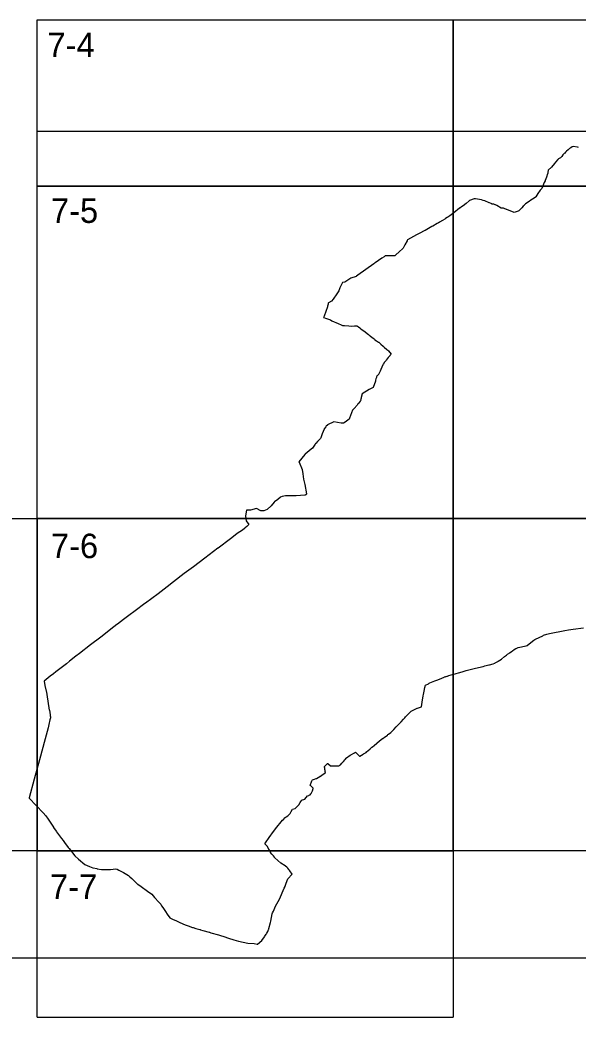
# Model space of a CAD drawing. Extents: x -449577 to -425530, y -1150048 to -1121091.
# Drawn here: x -431675.5 to -431465.8, y -1126653.4 to -1126278.4 of the extents above; entities that cross this region are included whole.
import ezdxf

# ---------------------------------------------------------------- set-up
doc = ezdxf.new("R2010")
doc.units = 0
for name, color, linetype in [('Vrstva 1', 7, 'Continuous'), ('Vrstva 10', 7, 'Continuous'), ('Vrstva 4', 7, 'Continuous')]:
    doc.layers.add(name, color=color, linetype=linetype)

msp = doc.modelspace()

# ---------------------------------------------------------------- linework, layer by layer
at = {"layer": 'Vrstva 1'}
for points in [[(-431465.6, -1126326.41), (-431466.06, -1126326.32), (-431467.65, -1126326), (-431467.95, -1126326.11), (-431468.51, -1126326.46), (-431469.06, -1126326.78), (-431469.55, -1126327.24), (-431470.08, -1126327.73), (-431470.48, -1126328.12), (-431470.49, -1126328.13), (-431470.82, -1126328.47), (-431470.95, -1126328.61), (-431471.46, -1126329.16), (-431471.91, -1126329.71), (-431472.07, -1126329.9), (-431472.43, -1126330.33), (-431473.17, -1126330.66), (-431473.19, -1126330.66), (-431473.39, -1126330.91), (-431474.25, -1126331.93), (-431474.63, -1126332.38), (-431475.76, -1126333.74), (-431475.77, -1126333.75), (-431477.01, -1126334.92), (-431477.13, -1126335.76), (-431477.18, -1126336.13), (-431477.22, -1126336.23), (-431477.7, -1126337.58), (-431478.14, -1126338.82), (-431478.17, -1126338.9), (-431478.47, -1126339.59), (-431479.4, -1126341.77), (-431479.42, -1126341.78), (-431479.99, -1126342.46), (-431480.29, -1126342.81), (-431480.29, -1126342.82), (-431480.63, -1126343.36), (-431481.5, -1126344.75), (-431481.59, -1126344.89), (-431481.76, -1126345.02), (-431482.29, -1126345.41), (-431482.9, -1126345.86), (-431482.9, -1126345.86), (-431483.87, -1126346.49), (-431484, -1126346.58), (-431484.18, -1126346.7), (-431485.48, -1126347.56), (-431485.49, -1126347.57), (-431485.75, -1126347.83), (-431485.87, -1126347.95), (-431486.09, -1126348.18), (-431486.37, -1126348.46), (-431486.94, -1126349.03), (-431488.1, -1126350.19), (-431488.3, -1126350.27), (-431489.8, -1126350.84), (-431492.61, -1126349.72), (-431492.61, -1126349.73), (-431492.62, -1126349.75), (-431493.53, -1126349.37), (-431493.84, -1126349.24), (-431493.86, -1126349.24), (-431494.25, -1126349.24), (-431494.73, -1126349.24), (-431496.29, -1126348.25), (-431496.55, -1126348.12), (-431496.84, -1126347.96), (-431496.9, -1126347.93), (-431496.94, -1126347.91), (-431497.48, -1126347.68), (-431497.53, -1126347.68), (-431497.54, -1126347.68), (-431497.69, -1126347.67), (-431497.81, -1126347.66), (-431498.12, -1126347.64), (-431498.14, -1126347.64), (-431498.14, -1126347.64), (-431498.25, -1126347.6), (-431498.49, -1126347.5), (-431499.09, -1126347.25), (-431499.25, -1126347.18), (-431500.77, -1126346.45), (-431501.39, -1126346.27), (-431502.06, -1126346.07), (-431504.38, -1126345.64), (-431504.39, -1126345.64), (-431504.79, -1126345.75), (-431506.53, -1126346.33), (-431506.66, -1126346.44), (-431507.87, -1126347.4), (-431507.87, -1126347.4), (-431509.02, -1126348.27), (-431509.59, -1126348.7), (-431510.17, -1126349.14), (-431510.33, -1126349.26), (-431512.46, -1126350.9), (-431513.53, -1126351.72), (-431514, -1126352.06), (-431514.76, -1126352.57), (-431515.01, -1126352.73), (-431515.6, -1126353.12), (-431515.64, -1126353.15), (-431515.85, -1126353.29), (-431516.76, -1126353.89), (-431516.77, -1126353.89), (-431517.24, -1126354.15), (-431517.39, -1126354.23), (-431517.57, -1126354.33), (-431518.03, -1126354.58), (-431518.21, -1126354.69), (-431518.37, -1126354.78), (-431518.47, -1126354.84), (-431518.71, -1126354.98), (-431520.37, -1126355.92), (-431520.54, -1126356.01), (-431520.77, -1126356.14), (-431523.24, -1126357.54), (-431523.36, -1126357.61), (-431525.47, -1126358.74), (-431526.49, -1126359.29), (-431529.83, -1126361.1), (-431530, -1126361.4), (-431530.06, -1126361.51), (-431530.84, -1126362.97), (-431531.52, -1126364.29), (-431531.66, -1126364.42), (-431531.75, -1126364.5), (-431532.89, -1126365.54), (-431534.4, -1126366.92), (-431534.57, -1126367.07), (-431534.57, -1126367.08), (-431535.04, -1126367.09), (-431538.23, -1126367.18), (-431538.24, -1126367.18), (-431538.67, -1126367.47), (-431539.5, -1126368.04), (-431541.97, -1126369.7), (-431542.01, -1126369.72), (-431542.25, -1126369.9), (-431542.52, -1126370.1), (-431545.5, -1126372.23), (-431545.57, -1126372.28), (-431548.57, -1126374.46), (-431549.04, -1126374.8), (-431549.2, -1126374.86), (-431551.14, -1126375.58), (-431551.15, -1126375.58), (-431551.54, -1126375.82), (-431553.42, -1126376.98), (-431554.34, -1126377.19), (-431554.59, -1126377.7), (-431555.35, -1126379.21), (-431555.36, -1126379.22), (-431555.43, -1126379.48), (-431555.63, -1126380.32), (-431556.46, -1126381.43), (-431557.83, -1126383.38), (-431558.39, -1126384.19), (-431558.42, -1126384.21), (-431559.58, -1126384.85), (-431559.68, -1126384.91), (-431559.75, -1126385.3), (-431559.9, -1126386.11), (-431559.95, -1126386.3), (-431561.24, -1126389.88), (-431561.41, -1126390.36), (-431561.38, -1126390.35), (-431561.36, -1126390.34), (-431560.68, -1126390.6), (-431558.87, -1126391.26), (-431558.25, -1126391.55), (-431555.96, -1126392.63), (-431555.94, -1126392.63), (-431554.78, -1126393.1), (-431554.31, -1126393.28), (-431554.28, -1126393.29), (-431553.85, -1126393.32), (-431553.71, -1126393.33), (-431553.49, -1126393.35), (-431551.89, -1126393.45), (-431550.85, -1126393.52), (-431549.8, -1126393.49), (-431548.96, -1126393.46), (-431548.95, -1126393.46), (-431548.67, -1126393.61), (-431548.3, -1126393.87), (-431547.75, -1126394.25), (-431547.36, -1126394.53), (-431545.8, -1126395.67), (-431545.63, -1126395.79), (-431544.52, -1126396.71), (-431544.13, -1126397.03), (-431543.95, -1126397.18), (-431543.2, -1126397.79), (-431542.93, -1126398.02), (-431542.33, -1126398.51), (-431542.11, -1126398.69), (-431541.47, -1126399.11), (-431540.72, -1126399.61), (-431540.69, -1126399.63), (-431539.93, -1126400.31), (-431539.05, -1126401.09), (-431538.61, -1126401.47), (-431537.6, -1126402.36), (-431537.34, -1126402.59), (-431537.29, -1126402.64), (-431537.19, -1126402.74), (-431537.18, -1126402.75), (-431537.09, -1126402.85), (-431537.06, -1126402.88), (-431536.01, -1126404.11), (-431536.02, -1126404.12), (-431536.46, -1126404.61), (-431536.52, -1126404.68), (-431537.09, -1126405.31), (-431537.91, -1126406.37), (-431538.08, -1126406.58), (-431538.64, -1126407.3), (-431538.94, -1126407.83), (-431538.96, -1126407.87), (-431538.97, -1126407.89), (-431539.1, -1126408.17), (-431539.9, -1126409.84), (-431540.21, -1126410.48), (-431540.83, -1126411.77), (-431540.94, -1126412.01), (-431540.95, -1126412.01), (-431540.99, -1126412.04), (-431541.28, -1126412.24), (-431541.36, -1126412.28), (-431541.41, -1126412.38), (-431541.5, -1126412.58), (-431541.59, -1126412.86), (-431541.76, -1126413.42), (-431541.77, -1126413.44), (-431541.89, -1126413.94), (-431541.91, -1126414.01), (-431541.9, -1126414.07), (-431541.89, -1126414.15), (-431541.89, -1126414.22), (-431541.9, -1126414.27), (-431542.78, -1126416.6), (-431542.8, -1126416.65), (-431542.82, -1126416.69), (-431542.83, -1126416.7), (-431543.53, -1126417), (-431543.78, -1126417.11), (-431544.25, -1126417.35), (-431546.86, -1126419.04), (-431546.86, -1126419.04), (-431547.23, -1126420.35), (-431547.31, -1126420.61), (-431547.42, -1126421.03), (-431547.48, -1126421.24), (-431547.48, -1126421.25), (-431547.47, -1126421.25), (-431547.3, -1126421.41), (-431547.31, -1126421.42), (-431547.67, -1126421.81), (-431548.47, -1126422.81), (-431548.48, -1126422.82), (-431548.69, -1126423.07), (-431548.69, -1126423.08), (-431548.81, -1126423.23), (-431549.97, -1126424.58), (-431550.51, -1126425.21), (-431551.27, -1126427.16), (-431551.65, -1126428.18), (-431551.78, -1126428.53), (-431553.31, -1126429.63), (-431553.93, -1126430.07), (-431554.11, -1126430.11), (-431554.13, -1126430.11), (-431554.76, -1126430.02), (-431557.6, -1126429.6), (-431558.09, -1126429.84), (-431559.42, -1126430.48), (-431559.96, -1126430.74), (-431559.99, -1126430.77), (-431560.42, -1126431.18), (-431560.59, -1126431.4), (-431561.25, -1126432.25), (-431561.25, -1126432.26), (-431561.92, -1126434.06), (-431562.49, -1126435.56), (-431562.49, -1126435.56), (-431562.63, -1126435.78), (-431562.96, -1126436.15), (-431563.68, -1126436.95), (-431564.38, -1126437.72), (-431564.39, -1126437.74), (-431564.52, -1126437.93), (-431565.59, -1126439.5), (-431566.06, -1126439.88), (-431567.63, -1126441.14), (-431568.3, -1126441.68), (-431568.4, -1126441.76), (-431568.43, -1126441.8), (-431569.55, -1126443.23), (-431570.69, -1126444.54), (-431570.54, -1126444.71), (-431570.53, -1126444.74), (-431570.53, -1126444.75), (-431569.52, -1126447.51), (-431569.24, -1126449.17), (-431568.92, -1126451.12), (-431568.51, -1126453.08), (-431567.78, -1126456.58), (-431567.74, -1126456.78), (-431568.39, -1126457.12), (-431568.51, -1126457.19), (-431571.68, -1126457.45), (-431571.84, -1126457.45), (-431573.33, -1126457.42), (-431575.72, -1126457.4), (-431577, -1126457.67), (-431577.6, -1126457.94), (-431578.58, -1126458.74), (-431579.88, -1126459.61), (-431579.97, -1126459.72), (-431581.13, -1126461.14), (-431582.58, -1126462.48), (-431583.27, -1126462.8), (-431583.87, -1126463.08), (-431585.04, -1126463.01), (-431586.65, -1126462.16), (-431588.89, -1126462.83), (-431590.37, -1126462.8), (-431590.75, -1126464.91), (-431590.76, -1126464.93), (-431590.77, -1126465.02), (-431590.48, -1126466.83), (-431589.51, -1126468.15), (-431589.5, -1126468.17), (-431590.24, -1126468.92), (-431590.85, -1126469.48), (-431591.1, -1126469.71), (-431591.9, -1126470.34), (-431593.83, -1126471.57), (-431593.89, -1126471.61), (-431595.86, -1126473.14), (-431595.92, -1126473.18), (-431596.41, -1126473.56), (-431601.07, -1126477.02), (-431601.1, -1126477.05), (-431606.05, -1126480.81), (-431610.31, -1126484.06), (-431611.19, -1126484.72), (-431613.76, -1126486.66), (-431617.76, -1126489.79), (-431620.2, -1126491.66), (-431623.51, -1126494.19), (-431623.56, -1126494.23), (-431628.35, -1126497.74), (-431628.58, -1126497.92), (-431632.19, -1126500.6), (-431634.58, -1126502.42), (-431636.55, -1126503.9), (-431638.87, -1126505.65), (-431639.1, -1126505.82), (-431640.23, -1126506.71), (-431645.05, -1126510.51), (-431648.94, -1126513.46), (-431653.16, -1126516.71), (-431654.45, -1126517.71), (-431656.84, -1126519.59), (-431658.02, -1126520.51), (-431661.96, -1126523.56), (-431662.89, -1126524.27), (-431664.13, -1126525.23), (-431666.45, -1126527.03), (-431666.45, -1126527.03), (-431666.41, -1126527.21), (-431666.12, -1126528.59), (-431666.09, -1126528.75), (-431665.56, -1126531.29), (-431665.4, -1126532.02), (-431665.4, -1126532.06), (-431664.47, -1126537.94), (-431664.46, -1126537.97), (-431664.16, -1126539.7), (-431664.16, -1126539.72), (-431664.1, -1126540.09), (-431664.04, -1126540.51), (-431664.07, -1126540.88), (-431664.22, -1126541.61), (-431664.6, -1126543.4), (-431664.89, -1126544.58), (-431664.91, -1126544.63), (-431666.02, -1126548.8), (-431668.12, -1126556.68), (-431670.11, -1126563.9), (-431672.04, -1126571), (-431672.05, -1126571.04), (-431666.77, -1126576.64), (-431665.72, -1126577.77), (-431664.96, -1126578.99), (-431662.94, -1126582.05), (-431662.89, -1126582.12), (-431661.88, -1126583.53), (-431661.72, -1126583.74), (-431659.84, -1126586.22), (-431659.27, -1126586.96), (-431659.24, -1126587), (-431658.72, -1126587.72), (-431657.34, -1126589.62), (-431657.01, -1126590.07), (-431654.86, -1126592.79), (-431653.46, -1126594.01), (-431651.06, -1126595.99), (-431649.32, -1126596.74), (-431648.13, -1126597.26), (-431648, -1126597.31), (-431646.67, -1126597.59), (-431646.53, -1126597.62), (-431644.91, -1126597.95), (-431644.88, -1126597.95), (-431643.92, -1126597.93), (-431643.54, -1126597.93), (-431643.02, -1126597.92), (-431642.34, -1126597.91), (-431641.43, -1126597.87), (-431639.48, -1126597.71), (-431639.03, -1126597.78), (-431638.37, -1126598.13), (-431636.65, -1126599.08), (-431634.69, -1126600.18), (-431634.17, -1126600.66), (-431633.45, -1126601.34), (-431632.65, -1126602.09), (-431631.33, -1126603.39), (-431631.19, -1126603.49), (-431630, -1126604.34), (-431627.59, -1126606.05), (-431625.95, -1126607.23), (-431624.9, -1126608.41), (-431623.26, -1126610.23), (-431622.62, -1126610.94), (-431622.26, -1126611.53), (-431621.8, -1126612.27), (-431620.86, -1126613.74), (-431620.23, -1126614.66), (-431619.19, -1126616.1), (-431618.12, -1126616.61), (-431616.74, -1126617.26), (-431615.43, -1126617.87), (-431613.46, -1126618.76), (-431612.33, -1126619.11), (-431610.61, -1126619.68), (-431610.46, -1126619.73), (-431609.37, -1126620.05), (-431607.95, -1126620.47), (-431607.94, -1126620.47), (-431607.73, -1126620.53), (-431607.67, -1126620.55), (-431606.81, -1126620.81), (-431604.42, -1126621.5), (-431604.3, -1126621.54), (-431603.82, -1126621.68), (-431600.89, -1126622.55), (-431598.2, -1126623.38), (-431597.86, -1126623.48), (-431597.1, -1126623.71), (-431595.09, -1126624.33), (-431593.36, -1126624.88), (-431589.9, -1126625.62)], [(-431589.9, -1126625.62), (-431587.51, -1126625.81), (-431586.31, -1126626.04), (-431586.2, -1126625.95), (-431584.62, -1126624.68), (-431583.59, -1126623.2), (-431583.48, -1126623.05), (-431582.96, -1126622.29), (-431582.85, -1126622.12), (-431582.71, -1126621.89), (-431582.33, -1126621.26), (-431582.06, -1126620.43), (-431582.04, -1126620.36), (-431582.02, -1126620.31), (-431581.99, -1126620.2), (-431581.96, -1126620.11), (-431581.96, -1126620.1), (-431581.33, -1126617.9), (-431581.19, -1126617.38), (-431580.74, -1126614.63), (-431580.74, -1126614.63), (-431580.55, -1126614.19), (-431580.29, -1126613.57), (-431579.5, -1126611.74), (-431577.93, -1126609.09), (-431576.18, -1126604.96), (-431575.86, -1126604.32), (-431575.82, -1126604.19), (-431575.43, -1126603.09), (-431574.84, -1126601.42), (-431573.16, -1126599.71), (-431574.09, -1126598.47), (-431574.15, -1126598.38), (-431574.2, -1126598.32), (-431574.23, -1126598.28), (-431574.3, -1126598.18), (-431574.35, -1126598.1), (-431574.43, -1126597.98), (-431574.79, -1126597.46), (-431575.16, -1126597), (-431575.73, -1126596.63), (-431575.83, -1126596.57), (-431577.48, -1126595.5), (-431579.67, -1126593.56), (-431579.8, -1126593.39), (-431579.83, -1126593.35), (-431579.91, -1126593.25), (-431580.25, -1126592.83), (-431580.58, -1126592.42), (-431580.84, -1126592.1), (-431581.32, -1126591.51), (-431581.4, -1126591.41), (-431581.9, -1126590.45), (-431582.19, -1126589.89), (-431582.42, -1126589.46), (-431582.47, -1126589.37), (-431582.51, -1126589.32), (-431582.77, -1126589.03), (-431582.97, -1126588.8), (-431583.23, -1126588.51), (-431583.45, -1126588.26), (-431581.59, -1126585.52), (-431581.5, -1126585.4), (-431581.18, -1126584.95), (-431580.86, -1126584.51), (-431579.53, -1126582.68), (-431576.85, -1126579.42), (-431576.5, -1126579.1), (-431575.79, -1126578.4), (-431575.68, -1126578.31), (-431575.49, -1126578.17), (-431574.89, -1126577.69), (-431574.03, -1126576.85), (-431573.62, -1126576.09), (-431573.15, -1126575.22), (-431572.1, -1126574.98), (-431570.7, -1126573.55), (-431570.16, -1126572.7), (-431570.15, -1126572.69), (-431570.15, -1126572.67), (-431569.94, -1126572.34), (-431569.89, -1126572.26), (-431569.65, -1126571.87), (-431568.49, -1126571.43), (-431567.47, -1126570.25), (-431566.94, -1126570.05), (-431566.82, -1126570), (-431566.4, -1126569.84), (-431566.18, -1126569.45), (-431566.13, -1126569.36), (-431565.96, -1126569.06), (-431565.55, -1126568.32), (-431565.35, -1126567.41), (-431565.35, -1126567.39), (-431565.34, -1126567.38), (-431566.39, -1126566.39), (-431566.41, -1126566.38), (-431566.42, -1126566.36), (-431566.47, -1126566.32), (-431565.82, -1126564.52), (-431565.75, -1126564.32), (-431565.59, -1126564.26), (-431564.86, -1126563.97), (-431564.17, -1126563.7), (-431564.05, -1126563.65), (-431562.84, -1126562.94), (-431562.72, -1126562.86), (-431562.72, -1126562.86), (-431562.71, -1126562.85), (-431562.59, -1126562.78), (-431560.73, -1126561.38), (-431560.73, -1126561.34), (-431560.76, -1126561.18), (-431560.83, -1126560.7), (-431560.89, -1126560.35), (-431560.99, -1126559.73), (-431561.01, -1126559.62), (-431561.03, -1126559.49), (-431561.05, -1126559.32), (-431561.08, -1126559.18), (-431560.54, -1126558.62), (-431559.98, -1126558.05), (-431559.94, -1126558), (-431559.8, -1126558.1), (-431558.8, -1126558.89), (-431558.12, -1126558.9), (-431558.06, -1126558.9), (-431557.81, -1126558.91), (-431557.65, -1126558.91), (-431556.34, -1126558.93), (-431555.71, -1126558.95), (-431555.44, -1126558.79), (-431555.41, -1126558.77), (-431555.29, -1126558.7), (-431555.15, -1126558.61), (-431555.11, -1126558.58), (-431554.57, -1126557.98), (-431554.46, -1126557.86), (-431554.37, -1126557.76), (-431554.2, -1126557.58), (-431554.12, -1126557.49), (-431554.01, -1126557.37), (-431553.98, -1126557.33), (-431553.95, -1126557.3), (-431553.9, -1126557.24), (-431553.81, -1126557.13), (-431553.41, -1126556.63), (-431553.2, -1126556.37), (-431552.95, -1126556.05), (-431552.84, -1126555.97), (-431551.38, -1126554.9), (-431551.17, -1126554.77), (-431549.81, -1126554), (-431549.41, -1126553.77), (-431549.41, -1126553.77), (-431549.27, -1126553.92), (-431548.56, -1126554.63), (-431548.19, -1126555.01), (-431548.01, -1126555.18), (-431547.86, -1126555.33), (-431547.77, -1126555.29), (-431546.49, -1126554.52), (-431546.4, -1126554.47), (-431545.47, -1126553.91), (-431545.43, -1126553.88), (-431545.1, -1126553.59), (-431545.05, -1126553.55), (-431544.88, -1126553.4), (-431544.87, -1126553.39), (-431544.87, -1126553.39), (-431544.83, -1126553.35), (-431544.79, -1126553.31), (-431543.9, -1126552.5), (-431543.88, -1126552.49), (-431543.29, -1126551.95), (-431543.18, -1126551.86), (-431543.07, -1126551.76), (-431543.07, -1126551.76), (-431543.06, -1126551.76), (-431543.06, -1126551.76), (-431543.06, -1126551.75), (-431543.05, -1126551.75), (-431543.04, -1126551.74), (-431543.04, -1126551.74), (-431543.03, -1126551.73), (-431543.03, -1126551.73), (-431543.02, -1126551.73), (-431543.02, -1126551.73), (-431542.44, -1126551.24), (-431540.45, -1126549.56), (-431539.25, -1126548.71), (-431539.13, -1126548.63), (-431539.08, -1126548.59), (-431539.06, -1126548.58), (-431539.01, -1126548.55), (-431538.65, -1126548.28), (-431537.41, -1126547.34), (-431537.23, -1126547.2), (-431537.02, -1126547.04), (-431537, -1126547.02), (-431536.12, -1126546.35), (-431535.77, -1126546.08), (-431535.72, -1126546.02), (-431535.63, -1126545.92), (-431534.99, -1126545.24), (-431534.09, -1126544.26), (-431532.73, -1126542.85), (-431532.51, -1126542.62), (-431532.26, -1126542.34), (-431531.42, -1126541.39), (-431531.13, -1126541.07), (-431530.93, -1126540.86), (-431530.64, -1126540.54), (-431529.46, -1126539.35), (-431528.53, -1126538.33), (-431526.47, -1126537.32), (-431526.31, -1126537.27), (-431526.11, -1126537.19), (-431524.67, -1126536.7), (-431524.52, -1126535.83), (-431524.36, -1126534.96), (-431523.94, -1126532.59), (-431523.86, -1126532.12), (-431523.53, -1126530.24), (-431523.33, -1126529.36), (-431523.3, -1126529.24), (-431523.25, -1126529.05), (-431523.24, -1126529.01), (-431523.22, -1126528.94), (-431523.21, -1126528.9), (-431523.2, -1126528.85), (-431523.19, -1126528.81), (-431523.18, -1126528.79), (-431523.12, -1126528.58), (-431522.04, -1126528.04), (-431521.75, -1126527.9), (-431521.73, -1126527.89), (-431521.48, -1126527.76), (-431521.43, -1126527.74), (-431519.66, -1126527.02), (-431519.63, -1126527.01), (-431519.6, -1126526.99), (-431518.8, -1126526.68), (-431517.84, -1126526.28), (-431517.03, -1126525.94), (-431516.09, -1126525.55), (-431516.01, -1126525.52), (-431515.4, -1126525.28), (-431515.55, -1126525.44), (-431515.31, -1126525.35), (-431514.82, -1126525.15), (-431514.29, -1126524.99), (-431512.59, -1126524.47), (-431512, -1126524.3), (-431511.55, -1126524.18), (-431510.66, -1126523.93), (-431509.35, -1126523.55), (-431507.81, -1126523.09), (-431504.27, -1126522.22), (-431501.5, -1126521.55), (-431500.83, -1126521.34), (-431499.34, -1126520.98), (-431499.13, -1126520.92), (-431497.7, -1126520.53), (-431497.1, -1126520.27), (-431496.88, -1126520.17), (-431496.72, -1126520.11), (-431495.9, -1126519.66), (-431495.84, -1126519.62), (-431494.53, -1126518.84), (-431493.38, -1126517.79), (-431492.73, -1126517.29), (-431492.6, -1126517.18), (-431492.58, -1126517.17), (-431492.42, -1126517.04), (-431492.27, -1126516.94), (-431491.47, -1126516.38), (-431491.41, -1126516.34), (-431491.34, -1126516.29), (-431490.83, -1126515.94), (-431490.46, -1126515.68), (-431489.8, -1126515.22), (-431489.21, -1126514.81), (-431489.05, -1126514.84), (-431489.04, -1126514.84), (-431489.02, -1126514.82), (-431488.29, -1126514.43), (-431485.33, -1126513.85), (-431484.91, -1126513.7), (-431482.88, -1126512.07), (-431482.41, -1126511.73), (-431482.38, -1126511.71), (-431482.02, -1126511.45), (-431481.84, -1126511.33), (-431480.45, -1126510.63), (-431479.04, -1126509.99), (-431478.74, -1126509.84), (-431477.48, -1126509.38), (-431476.48, -1126509.13), (-431470.77, -1126508.07), (-431469.35, -1126507.81), (-431467.64, -1126507.56), (-431463.77, -1126506.99)]]:
    msp.add_lwpolyline(points, dxfattribs=at)
at = {"layer": 'Vrstva 10'}
msp.add_lwpolyline([(-431356.51, -1126320.23), (-431356.51, -1126631.21), (-431689.38, -1126631.21), (-431689.38, -1126465.91), (-431669.01, -1126465.91), (-431669.01, -1126340.91), (-431669.01, -1126320.23), (-431356.51, -1126320.23)], dxfattribs=at)
at = {"layer": 'Vrstva 4'}
for p, q in [((-431669.01, -1126278.41), (-431356.51, -1126278.41)), ((-431669.01, -1126653.41), (-431512.76, -1126653.41))]:
    msp.add_line(p, q, dxfattribs=at)
for points in [[(-431512.76, -1126278.41), (-431512.76, -1126340.91), (-431669.01, -1126340.91), (-431669.01, -1126278.41)], [(-431356.51, -1126278.41), (-431356.51, -1126340.91), (-431512.76, -1126340.91), (-431512.76, -1126278.41)], [(-431747.14, -1126465.91), (-431669.01, -1126465.91), (-431669.01, -1126590.91), (-431747.14, -1126590.91)], [(-431669.01, -1126653.41), (-431669.01, -1126590.91), (-431512.76, -1126590.91), (-431512.76, -1126653.41)]]:
    msp.add_lwpolyline(points, dxfattribs=at)
for points in [[(-431512.76, -1126340.91), (-431512.76, -1126465.91), (-431669.01, -1126465.91), (-431669.01, -1126340.91)], [(-431356.51, -1126340.91), (-431356.51, -1126465.91), (-431512.76, -1126465.91), (-431512.76, -1126340.91)], [(-431512.76, -1126465.91), (-431512.76, -1126590.91), (-431669.01, -1126590.91), (-431669.01, -1126465.91)], [(-431356.51, -1126465.91), (-431356.51, -1126590.91), (-431512.76, -1126590.91), (-431512.76, -1126465.91)]]:
    msp.add_lwpolyline(points, close=True, dxfattribs=at)

# ---------------------------------------------------------------- texts
at = {"layer": 'Vrstva 1'}
for s, p in [('7-4', (-431665.2, -1126292.41)), ('7-5', (-431663.89, -1126354.75)), ('7-6', (-431663.89, -1126480.82)), ('7-7', (-431664.25, -1126608.99))]:
    msp.add_text(s, height=9.2, dxfattribs=at).set_placement(p)

doc.saveas('drawing.dxf')
